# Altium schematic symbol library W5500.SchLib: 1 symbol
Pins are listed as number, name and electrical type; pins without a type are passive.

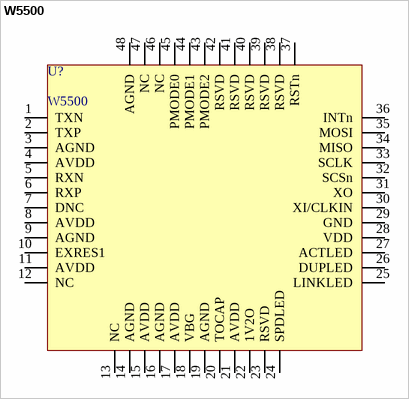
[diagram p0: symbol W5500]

## W5500
designator U?
footprint TQFP48_N (48-Pin Thin Quad Flat Pack 0.5 mm Pitch, IPC Medium Density)
pins: 1 TXN, 2 TXP, 3 AGND, 4 AVDD, 5 RXN, 6 RXP, 7 DNC, 8 AVDD, 9 AGND, 10 EXRES1, 11 AVDD, 12 NC, 13 NC, 14 AGND, 15 AVDD, 16 AGND, 17 AVDD, 18 VBG, 19 AGND, 20 TOCAP, 21 AVDD, 22 1V2O, 23 RSVD, 24 SPDLED, 25 LINKLED, 26 DUPLED, 27 ACTLED, 28 VDD, 29 GND, 30 XI/CLKIN, 31 XO, 32 SCSn, 33 SCLK, 34 MISO, 35 MOSI, 36 INTn, 37 RSTn, 38 RSVD, 39 RSVD, 40 RSVD, 41 RSVD, 42 RSVD, 43 PMODE2, 44 PMODE1, 45 PMODE0, 46 NC, 47 NC, 48 AGND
